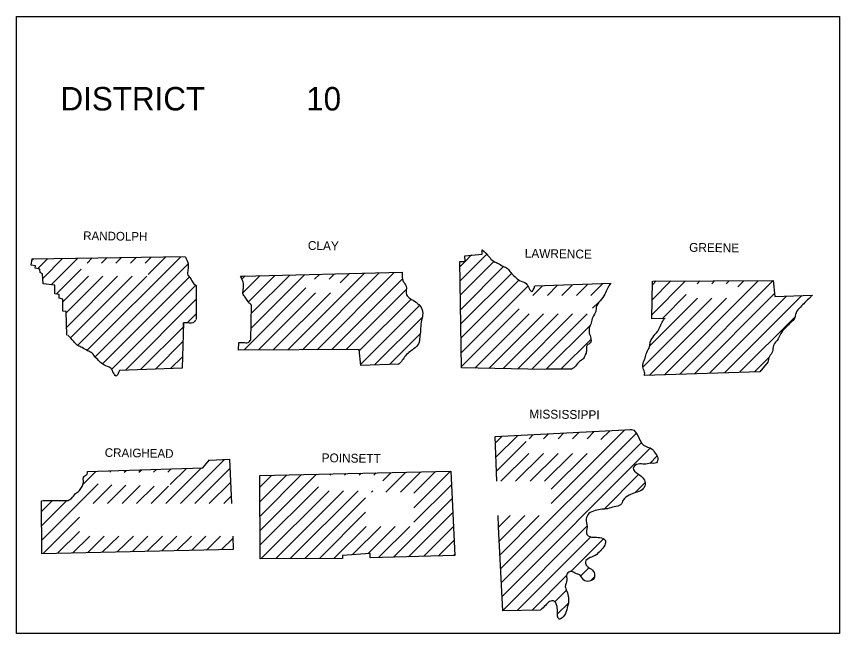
# Model space of a CAD drawing. Extents: x 76 to 6945, y -3933 to 2152.
# Drawn here: x 6541.2 to 6941.2, y -3562.8 to -3262.8 of the extents above; entities that cross this region are included whole.
import ezdxf

# ---------------------------------------------------------------- set-up
doc = ezdxf.new("R2010")
doc.units = 0
doc.layers.add('R_Draft', color=7, linetype='Continuous')

msp = doc.modelspace()

# ---------------------------------------------------------------- linework, layer by layer
at = {"layer": 'R_Draft'}
msp.add_lwpolyline([(6541.16, -3562.76), (6541.16, -3262.76), (6941.16, -3262.76), (6941.16, -3562.76)], close=True, dxfattribs=at)
for points in [[(6548.66, -3380.56), (6623.26, -3379.46)], [(6575.46, -3425.06), (6621.06, -3379.56)], [(6589.46, -3382.76), (6592.26, -3379.96)], [(6596.56, -3382.76), (6599.46, -3379.86)], [(6603.66, -3382.76), (6606.66, -3379.76)], [(6605.16, -3388.26), (6613.76, -3379.66)], [(6797.76, -3434.46), (6757.46, -3433.56), (6756.56, -3381.96), (6759.16, -3381.86), (6759.06, -3379.06), (6767.56, -3378.26), (6767.56, -3376.26)], [(6756.56, -3384.46), (6759.16, -3381.86), (6762.36, -3378.66)], [(6756.76, -3391.36), (6769.66, -3378.46)], [(6565.66, -3417.66), (6565.26, -3406.26), (6563.66, -3405.96), (6563.76, -3400.16), (6561.96, -3399.66), (6561.96, -3397.96), (6559.86, -3397.66), (6559.86, -3393.36), (6554.16, -3392.76), (6553.86, -3387.96), (6552.76, -3387.26), (6552.56, -3385.66), (6550.26, -3385.16), (6550.36, -3383.96), (6548.36, -3383.66), (6548.76, -3380.56)], [(6548.66, -3381.16), (6549.36, -3380.56)], [(6551.56, -3385.36), (6556.46, -3380.46)], [(6554.06, -3389.96), (6563.56, -3380.36)], [(6557.96, -3393.16), (6570.76, -3380.36)], [(6575.46, -3382.76), (6577.96, -3380.16)], [(6579.46, -3428.16), (6624.46, -3383.16)], [(6582.46, -3382.76), (6585.06, -3380.06)], [(6756.86, -3398.26), (6773.16, -3381.96)], [(6560.46, -3397.76), (6572.56, -3385.56)], [(6650.06, -3388.96), (6651.06, -3388.96), (6728.66, -3387.16)], [(6672.96, -3424.86), (6710.16, -3387.66)], [(6680.16, -3424.76), (6717.46, -3387.46)], [(6687.26, -3424.76), (6724.66, -3387.26)], [(6693.06, -3390.56), (6695.66, -3387.96)], [(6698.46, -3392.26), (6702.96, -3387.76)], [(6757.06, -3405.26), (6777.86, -3384.36)], [(6757.16, -3412.16), (6781.66, -3387.66)], [(6563.76, -3401.46), (6576.16, -3389.06)], [(6565.36, -3406.86), (6583.16, -3389.06)], [(6565.56, -3413.76), (6590.26, -3389.06)], [(6567.46, -3418.96), (6597.36, -3389.06)], [(6570.76, -3422.76), (6570.86, -3422.66), (6604.46, -3389.06)], [(6583.16, -3431.56), (6625.16, -3389.56)], [(6650.76, -3390.56), (6652.36, -3388.86)], [(6651.36, -3396.96), (6659.56, -3388.76)], [(6653.86, -3401.56), (6666.86, -3388.56)], [(6655.26, -3414.26), (6681.26, -3388.26)], [(6655.36, -3407.06), (6673.96, -3388.46)], [(6686.06, -3390.56), (6688.46, -3388.16)], [(6694.36, -3424.66), (6728.86, -3390.16)], [(6757.26, -3419.06), (6785.36, -3390.96)], [(6849.86, -3407.76), (6866.26, -3391.36)], [(6849.86, -3409.76), (6850.26, -3391.46)], [(6850.06, -3400.46), (6859.16, -3391.36)], [(6850.26, -3393.16), (6852.06, -3391.36)], [(6850.36, -3391.46), (6908.86, -3391.16), (6909.66, -3398.96), (6927.96, -3398.26)], [(6856.06, -3436.96), (6901.66, -3391.26)], [(6863.36, -3436.76), (6908.86, -3391.16)], [(6871.96, -3392.76), (6873.26, -3391.36)], [(6879.06, -3392.76), (6880.46, -3391.36)], [(6886.06, -3392.76), (6887.46, -3391.36)], [(6891.66, -3394.26), (6894.66, -3391.26)], [(6587.46, -3434.26), (6628.26, -3393.46)], [(6628.56, -3393.86), (6628.56, -3410.16)], [(6651.76, -3424.86), (6681.86, -3394.76)], [(6701.46, -3424.66), (6730.46, -3395.66)], [(6757.36, -3426.06), (6789.66, -3393.86)], [(6792.06, -3398.46), (6796.86, -3393.66)], [(6793.06, -3393.76), (6830.16, -3392.46)], [(6799.16, -3398.46), (6804.16, -3393.36)], [(6806.16, -3398.46), (6811.46, -3393.16)], [(6813.36, -3398.46), (6818.86, -3392.96)], [(6820.36, -3398.46), (6826.16, -3392.66)], [(6658.76, -3424.86), (6686.56, -3397.06)], [(6665.96, -3424.86), (6693.76, -3397.06)], [(6845.76, -3433.06), (6879.16, -3399.66)], [(6848.76, -3437.16), (6886.26, -3399.66)], [(6849.06, -3422.66), (6872.16, -3399.66)], [(6855.16, -3409.56), (6866.66, -3397.96)], [(6870.66, -3436.46), (6909.46, -3397.66)], [(6877.96, -3436.26), (6915.46, -3398.76)], [(6885.26, -3435.96), (6922.76, -3398.46)], [(6594.16, -3434.66), (6628.56, -3400.26)], [(6655.06, -3419.96), (6655.46, -3403.16)], [(6707.76, -3425.36), (6732.96, -3400.26)], [(6708.46, -3431.76), (6736.96, -3403.26)], [(6821.16, -3404.66), (6824.36, -3401.46)], [(6624.16, -3411.76), (6628.56, -3407.36)], [(6757.46, -3432.96), (6785.46, -3404.96)], [(6763.86, -3433.76), (6790.26, -3407.36)], [(6770.76, -3433.86), (6797.26, -3407.36)], [(6777.76, -3433.96), (6804.46, -3407.36)], [(6784.66, -3434.16), (6811.46, -3407.36)], [(6791.56, -3434.26), (6818.46, -3407.36)], [(6622.26, -3415.46), (6622.26, -3411.76), (6621.76, -3433.76)], [(6715.16, -3432.16), (6738.26, -3409.06)], [(6856.36, -3409.56), (6849.86, -3409.76)], [(6892.56, -3435.76), (6919.36, -3408.96)], [(6601.46, -3434.46), (6622.26, -3413.66), (6622.26, -3413.66)], [(6798.66, -3434.26), (6819.76, -3413.16)], [(6722.46, -3431.96), (6737.36, -3417.06)], [(6805.76, -3434.26), (6820.26, -3419.76)], [(6608.76, -3434.16), (6622.06, -3420.86)], [(6649.06, -3424.96), (6649.16, -3421.26)], [(6726.86, -3431.76), (6708.46, -3432.46), (6707.66, -3424.66), (6649.16, -3424.96)], [(6616.06, -3433.96), (6621.86, -3428.16)], [(6906.36, -3430.86), (6902.36, -3435.46), (6846.36, -3437.26)], [(6899.86, -3435.56), (6906.96, -3428.46)], [(6621.76, -3433.76), (6591.16, -3434.86)], [(6810.86, -3434.26), (6798.66, -3434.26), (6797.76, -3434.46)], [(6773.76, -3466.96), (6840.06, -3463.56)], [(6801.06, -3499.56), (6836.86, -3463.76)], [(6774.66, -3488.76), (6773.76, -3466.96)], [(6773.86, -3470.16), (6777.26, -3466.76)], [(6774.16, -3476.96), (6784.76, -3466.46)], [(6776.46, -3531.26), (6842.26, -3465.46), (6842.36, -3465.36)], [(6790.26, -3468.06), (6792.26, -3466.06)], [(6797.26, -3468.06), (6799.66, -3465.66)], [(6804.36, -3468.06), (6807.16, -3465.26)], [(6811.46, -3468.06), (6814.56, -3464.86)], [(6818.46, -3468.06), (6821.96, -3464.56)], [(6825.16, -3468.46), (6829.46, -3464.16)], [(6774.46, -3483.76), (6788.86, -3469.36)], [(6776.76, -3538.06), (6844.86, -3469.96)], [(6776.56, -3488.76), (6790.16, -3475.16)], [(6777.16, -3544.76), (6849.26, -3472.56)], [(6783.66, -3488.76), (6797.26, -3475.16)], [(6790.76, -3488.76), (6804.36, -3475.16)], [(6797.76, -3488.76), (6811.36, -3475.16)], [(6801.06, -3492.56), (6818.46, -3475.16)], [(6575.66, -3483.96), (6631.66, -3482.16), (6634.96, -3478.36)], [(6620.86, -3499.56), (6642.26, -3478.16)], [(6635.16, -3478.46), (6644.76, -3477.96)], [(6644.76, -3477.96), (6645.66, -3499.56)], [(6848.96, -3480.06), (6852.36, -3476.56)], [(6573.46, -3490.26), (6579.96, -3483.86)], [(6586.46, -3484.36), (6587.16, -3483.66)], [(6593.56, -3484.36), (6594.46, -3483.46)], [(6600.66, -3484.36), (6601.86, -3483.16)], [(6607.76, -3484.36), (6609.16, -3482.96)], [(6613.76, -3499.56), (6631.06, -3482.26)], [(6614.76, -3484.36), (6616.36, -3482.76)], [(6615.86, -3490.36), (6623.76, -3482.46)], [(6627.86, -3499.56), (6644.86, -3482.46)], [(6659.36, -3485.96), (6752.26, -3483.86)], [(6734.26, -3501.66), (6752.06, -3483.86)], [(6752.26, -3483.86), (6754.26, -3524.76)], [(6659.66, -3526.46), (6659.36, -3485.96)], [(6659.46, -3498.66), (6672.56, -3485.56)], [(6659.46, -3491.66), (6665.26, -3485.76)], [(6659.56, -3505.66), (6679.76, -3485.46)], [(6659.66, -3512.66), (6686.96, -3485.26)], [(6693.56, -3485.76), (6694.16, -3485.16)], [(6700.66, -3485.76), (6701.46, -3484.96)], [(6707.76, -3485.76), (6708.66, -3484.86)], [(6714.86, -3485.76), (6715.96, -3484.66)], [(6719.16, -3488.56), (6723.16, -3484.56)], [(6720.66, -3494.06), (6730.36, -3484.36)], [(6727.76, -3494.06), (6737.66, -3484.16)], [(6734.26, -3494.56), (6744.86, -3484.06)], [(6826.76, -3502.26), (6843.46, -3485.46)], [(6553.46, -3517.36), (6580.86, -3489.96)], [(6578.36, -3499.56), (6587.46, -3490.46)], [(6585.46, -3499.56), (6594.36, -3490.66)], [(6592.56, -3499.56), (6601.26, -3490.86)], [(6599.56, -3499.56), (6608.06, -3491.06)], [(6606.66, -3499.56), (6615.06, -3491.16)], [(6634.86, -3499.56), (6645.16, -3489.26)], [(6659.66, -3519.66), (6687.96, -3491.36)], [(6734.26, -3508.66), (6752.56, -3490.46)], [(6841.66, -3494.36), (6846.66, -3489.36)], [(6660.06, -3526.36), (6693.06, -3493.36)], [(6667.16, -3526.36), (6700.16, -3493.36)], [(6674.16, -3526.36), (6707.26, -3493.36)], [(6713.66, -3494.06), (6714.36, -3493.36)], [(6553.26, -3498.26), (6554.16, -3498.06), (6566.36, -3498.06)], [(6553.46, -3523.96), (6553.26, -3498.26)], [(6553.36, -3510.36), (6565.66, -3498.06)], [(6553.36, -3503.36), (6558.66, -3498.06)], [(6641.96, -3499.56), (6645.36, -3496.16)], [(6681.36, -3526.26), (6710.86, -3496.76)], [(6724.46, -3525.56), (6752.86, -3497.16)], [(6688.36, -3526.26), (6710.86, -3503.76)], [(6731.66, -3525.46), (6753.26, -3503.86)], [(6553.96, -3523.96), (6571.76, -3506.16)], [(6777.46, -3551.76), (6775.46, -3510.86), (6775.26, -3505.36)], [(6775.56, -3510.96), (6781.16, -3505.36)], [(6775.86, -3517.76), (6788.26, -3505.36)], [(6776.16, -3524.46), (6795.26, -3505.36)], [(6695.46, -3526.26), (6711.06, -3510.76)], [(6704.36, -3524.46), (6718.16, -3510.76)], [(6712.06, -3523.86), (6725.16, -3510.76)], [(6717.16, -3525.76), (6732.26, -3510.76)], [(6738.96, -3525.26), (6753.56, -3510.66)], [(6777.46, -3551.56), (6818.36, -3510.56)], [(6561.16, -3523.76), (6571.76, -3513.16)], [(6568.36, -3523.66), (6576.76, -3515.36)], [(6575.66, -3523.46), (6583.76, -3515.36)], [(6582.86, -3523.26), (6590.86, -3515.36)], [(6590.16, -3523.06), (6597.96, -3515.36)], [(6597.36, -3522.96), (6605.06, -3515.36)], [(6604.66, -3522.76), (6612.06, -3515.36)], [(6611.86, -3522.56), (6619.06, -3515.36)], [(6619.06, -3522.46), (6626.16, -3515.36)], [(6626.26, -3522.36), (6633.26, -3515.36)], [(6633.56, -3522.16), (6640.36, -3515.36)], [(6646.26, -3515.36), (6646.46, -3521.86)], [(6784.46, -3551.56), (6820.26, -3515.76)], [(6640.76, -3521.96), (6646.26, -3516.56)], [(6746.26, -3525.06), (6753.86, -3517.36)], [(6810.66, -3532.46), (6826.46, -3516.66)], [(6646.46, -3521.86), (6553.46, -3523.96)], [(6754.26, -3524.76), (6713.06, -3525.96), (6713.06, -3523.86), (6699.66, -3524.86), (6699.56, -3526.26), (6659.66, -3526.46)], [(6753.56, -3524.86), (6754.26, -3524.16)], [(6815.46, -3534.66), (6819.56, -3530.66)], [(6791.76, -3551.36), (6808.66, -3534.46)], [(6820.06, -3537.16), (6822.06, -3535.16)], [(6802.86, -3547.36), (6808.46, -3541.66)], [(6804.06, -3553.16), (6809.36, -3547.96)], [(6795.76, -3551.36), (6777.46, -3551.76)]]:
    msp.add_lwpolyline(points, dxfattribs=at)
for points in [[(6623.26, -3379.76), (6624.56, -3383.26), (6624.46, -3385.96), (6624.46, -3388.46), (6625.76, -3390.16), (6627.06, -3392.26), (6628.76, -3393.76)], [(6767.56, -3376.26), (6770.86, -3379.66), (6772.76, -3381.56), (6774.96, -3382.66), (6777.56, -3384.16), (6779.86, -3385.36), (6781.36, -3387.26), (6783.46, -3389.36), (6785.56, -3391.06), (6788.86, -3392.66), (6789.96, -3394.36), (6791.46, -3396.46), (6793.06, -3393.76)], [(6728.66, -3387.16), (6729.16, -3391.56), (6730.56, -3393.86), (6730.76, -3398.06), (6732.46, -3399.86), (6735.36, -3401.66), (6737.96, -3404.56), (6738.56, -3407.96), (6737.76, -3411.46), (6737.56, -3415.36), (6737.16, -3418.76), (6736.56, -3421.86), (6734.16, -3424.36), (6731.86, -3426.16), (6729.76, -3428.26), (6728.26, -3430.46), (6726.66, -3431.96)], [(6728.66, -3387.16), (6729.16, -3391.56), (6730.56, -3393.86), (6730.76, -3398.06), (6732.46, -3399.86), (6735.36, -3401.66), (6737.96, -3404.56), (6738.56, -3407.96), (6737.76, -3411.46), (6737.56, -3415.36), (6737.16, -3418.76), (6736.56, -3421.86), (6734.16, -3424.36), (6731.86, -3426.16), (6729.76, -3428.26), (6728.26, -3430.46), (6726.66, -3431.96)], [(6655.46, -3403.16), (6653.96, -3401.76), (6652.66, -3399.66), (6651.36, -3397.96), (6651.36, -3395.46), (6651.46, -3392.76), (6650.06, -3388.96)], [(6829.86, -3392.56), (6828.36, -3394.96), (6827.16, -3397.76), (6824.76, -3400.96), (6822.96, -3404.06), (6822.66, -3406.16), (6821.26, -3408.96), (6820.46, -3411.76), (6819.56, -3414.16), (6819.56, -3416.66), (6820.26, -3419.16), (6820.06, -3421.46), (6818.56, -3422.56), (6818.16, -3425.46), (6817.56, -3427.46), (6816.26, -3429.46), (6814.36, -3430.96), (6812.36, -3433.26), (6810.86, -3434.26)], [(6927.96, -3398.26), (6926.86, -3399.36), (6924.26, -3401.86), (6922.16, -3404.06), (6920.06, -3406.86), (6919.06, -3409.96), (6916.76, -3412.16), (6914.96, -3414.16), (6912.56, -3416.86), (6911.36, -3419.56), (6909.06, -3422.66), (6908.56, -3425.66), (6907.06, -3428.06), (6906.36, -3430.86)], [(6927.96, -3398.26), (6926.86, -3399.36), (6924.26, -3401.86), (6922.16, -3404.06), (6920.06, -3406.86), (6919.06, -3409.96), (6916.76, -3412.16), (6914.96, -3414.16), (6912.56, -3416.86), (6911.36, -3419.56), (6909.06, -3422.66), (6908.56, -3425.66), (6907.06, -3428.06), (6906.36, -3430.86)], [(6628.16, -3410.46), (6626.86, -3411.76), (6624.36, -3411.76), (6622.26, -3411.76)], [(6846.36, -3437.26), (6846.46, -3436.26), (6845.76, -3433.76), (6845.76, -3431.26), (6846.66, -3428.86), (6847.46, -3426.06), (6848.86, -3423.26), (6849.16, -3421.16), (6850.96, -3418.06), (6853.36, -3414.86), (6854.56, -3412.06), (6856.06, -3409.66)], [(6591.16, -3434.86), (6589.56, -3437.56), (6588.06, -3435.46), (6586.96, -3433.76), (6583.66, -3432.16), (6581.56, -3430.46), (6579.46, -3428.36), (6577.96, -3426.46), (6575.66, -3425.26), (6573.06, -3423.76), (6570.86, -3422.66), (6568.96, -3420.76), (6566.06, -3417.66)], [(6649.16, -3421.26), (6651.26, -3421.26), (6653.76, -3421.26), (6655.06, -3419.96)], [(6838.96, -3463.66), (6840.06, -3463.56), (6843.46, -3467.16), (6844.96, -3470.16), (6847.16, -3471.86), (6849.66, -3472.76), (6851.56, -3475.06), (6852.86, -3477.56), (6852.16, -3479.76), (6849.36, -3479.96), (6846.26, -3480.46), (6843.26, -3480.36), (6840.86, -3482.36), (6843.06, -3485.06), (6845.96, -3487.56), (6846.76, -3490.26), (6845.16, -3492.86), (6841.96, -3494.26), (6838.86, -3495.46), (6836.06, -3497.86), (6834.76, -3500.16), (6831.66, -3501.16), (6828.46, -3502.06), (6825.66, -3502.36), (6822.46, -3502.96), (6819.36, -3504.46), (6818.06, -3507.06), (6818.46, -3510.76), (6818.36, -3514.66), (6821.66, -3515.96), (6824.56, -3516.06), (6827.36, -3517.56), (6827.06, -3519.76), (6824.96, -3522.56), (6822.46, -3524.76), (6819.96, -3525.86), (6817.66, -3527.96), (6818.46, -3530.06), (6820.56, -3531.46), (6822.06, -3533.76), (6821.86, -3535.86), (6819.46, -3537.36), (6816.86, -3536.76), (6814.96, -3534.26), (6812.76, -3533.46), (6810.86, -3532.56), (6808.66, -3533.86), (6808.66, -3536.76), (6807.86, -3539.86), (6808.56, -3542.16), (6809.46, -3545.36), (6809.36, -3547.76), (6808.56, -3551.16), (6806.86, -3554.66), (6804.86, -3555.76), (6804.06, -3551.96), (6803.66, -3548.86), (6802.46, -3547.06), (6800.86, -3546.96), (6798.76, -3548.46), (6796.46, -3550.76), (6795.86, -3551.26)], [(6838.96, -3463.66), (6840.06, -3463.56), (6843.46, -3467.16), (6844.96, -3470.16), (6847.16, -3471.86), (6849.66, -3472.76), (6851.56, -3475.06), (6852.86, -3477.56), (6852.16, -3479.76), (6849.36, -3479.96), (6846.26, -3480.46), (6843.26, -3480.36), (6840.86, -3482.36), (6843.06, -3485.06), (6845.96, -3487.56), (6846.76, -3490.26), (6845.16, -3492.86), (6841.96, -3494.26), (6838.86, -3495.46), (6836.06, -3497.86), (6834.76, -3500.16), (6831.66, -3501.16), (6828.46, -3502.06), (6825.66, -3502.36), (6822.46, -3502.96), (6819.36, -3504.46), (6818.06, -3507.06), (6818.46, -3510.76), (6818.36, -3514.66), (6821.66, -3515.96), (6824.56, -3516.06), (6827.36, -3517.56), (6827.06, -3519.76), (6824.96, -3522.56), (6822.46, -3524.76), (6819.96, -3525.86), (6817.66, -3527.96), (6818.46, -3530.06), (6820.56, -3531.46), (6822.06, -3533.76), (6821.86, -3535.86), (6819.46, -3537.36), (6816.86, -3536.76), (6814.96, -3534.26), (6812.76, -3533.46), (6810.86, -3532.56), (6808.66, -3533.86), (6808.66, -3536.76), (6807.86, -3539.86), (6808.56, -3542.16), (6809.46, -3545.36), (6809.36, -3547.76), (6808.56, -3551.16), (6806.86, -3554.66), (6804.86, -3555.76), (6804.06, -3551.96), (6803.66, -3548.86), (6802.46, -3547.06), (6800.86, -3546.96), (6798.76, -3548.46), (6796.46, -3550.76), (6795.86, -3551.26)], [(6566.36, -3498.06), (6567.86, -3497.06), (6569.86, -3494.76), (6571.76, -3493.26), (6573.06, -3491.26), (6573.66, -3489.26), (6574.06, -3486.36), (6575.56, -3485.26), (6575.66, -3483.96)]]:
    msp.add_spline(points, degree=3, dxfattribs=at)

# ---------------------------------------------------------------- texts
for s, p in [('DISTRICT', (6562.56, -3308.46)), ('10', (6681.96, -3308.46))]:
    msp.add_text(s, height=11.4, dxfattribs=at).set_placement(p)
for s, height, rotation, p in [('RANDOLPH', 4.201, 359.2583, (6573.56, -3371.46)), ('CLAY', 4.3, 359.2258, (6682.76, -3376.26)), ('LAWRENCE', 4.301, 359.2678, (6788.16, -3380.06)), ('GREENE', 4.301, 359.2361, (6868.06, -3377.16)), ('MISSISSIPPI', 4.2996, 359.3097, (6790.36, -3458.16)), ('CRAIGHEAD', 4.201, 359.1159, (6584.06, -3476.86)), ('POINSETT', 4.3, 359.1987, (6689.46, -3479.46))]:
    msp.add_text(s, height=height, rotation=rotation, dxfattribs=at).set_placement(p)

doc.saveas('drawing.dxf')
